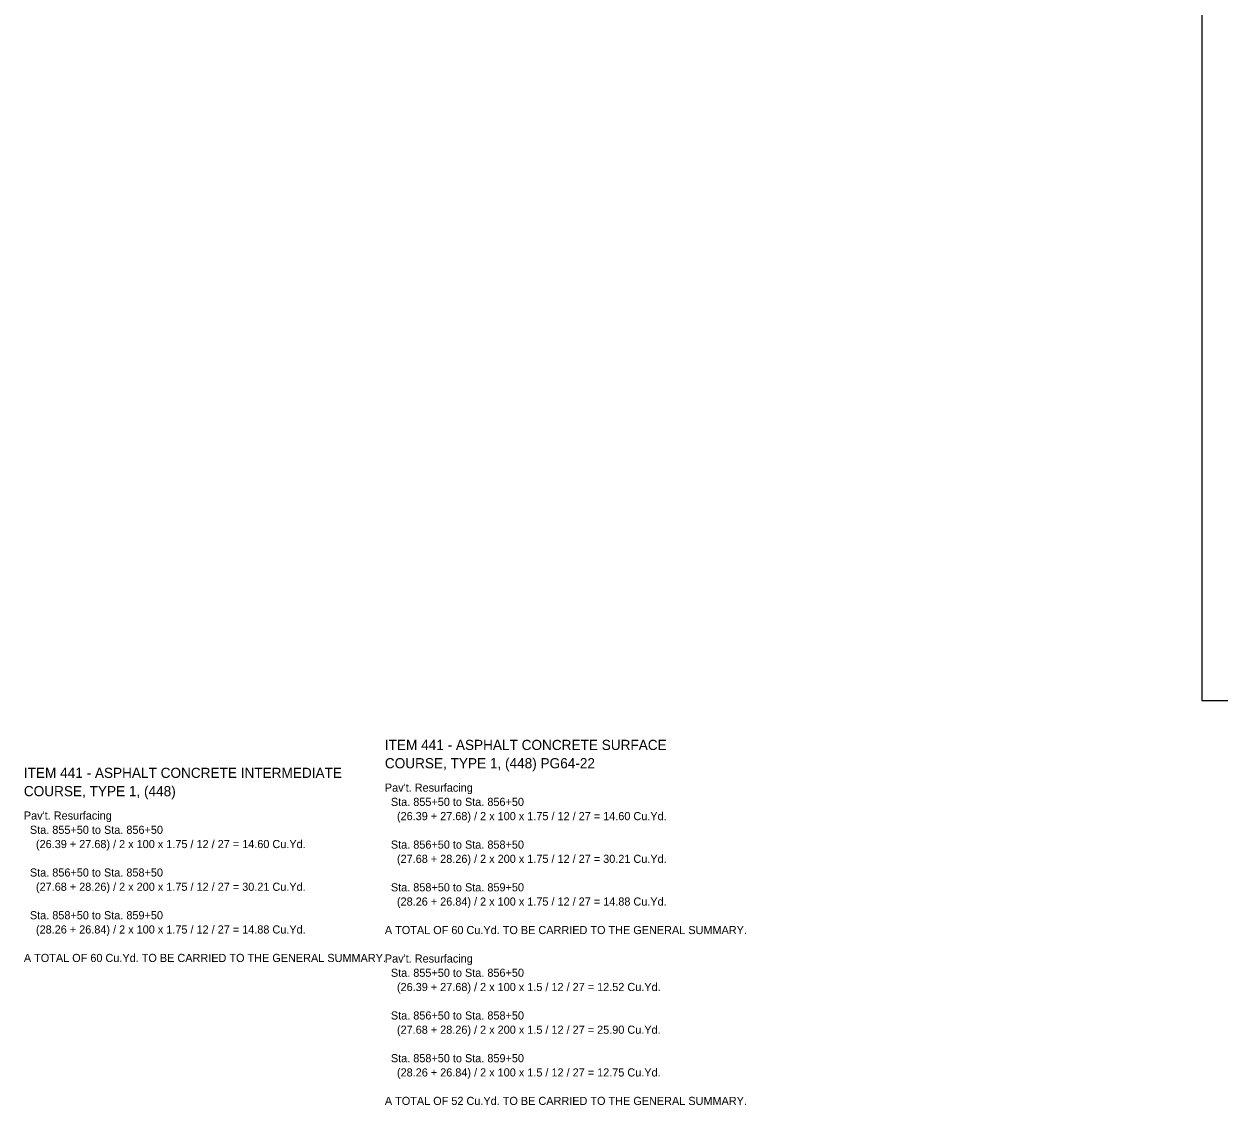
# Model space of a CAD drawing. Extents: x -40.7 to 43.6, y -9.8 to 57.4.
# Drawn here: x -23.17 to 0.34, y -7.95 to 13.31 of the extents above; entities that cross this region are included whole.
import ezdxf

# ---------------------------------------------------------------- set-up
doc = ezdxf.new("R2010")
doc.units = 0
doc.layers.add('Default', color=7, linetype='Continuous')
doc.layers.add('SH_Cut_Line', color=7, linetype='Continuous')

msp = doc.modelspace()

# ---------------------------------------------------------------- linework, layer by layer
at = {"layer": 'SH_Cut_Line'}
msp.add_lwpolyline([(0, 0), (34, 0), (34, 22), (0, 22)], close=True, dxfattribs=at)

# ---------------------------------------------------------------- texts
at = {"layer": 'Default'}
for s, height, p in [('ITEM 441 - ASPHALT CONCRETE SURFACE', 0.2, (-16.07, -0.971)), ('COURSE, TYPE 1, (448) PG64-22', 0.2, (-16.07, -1.331)), ('ITEM 441 - ASPHALT CONCRETE INTERMEDIATE', 0.2, (-23.17, -1.52)), ("Pav't. Resurfacing", 0.16, (-16.07, -1.791)), ('COURSE, TYPE 1, (448)', 0.2, (-23.17, -1.88)), ('  Sta. 855+50 to Sta. 856+50', 0.16, (-16.07, -2.071)), ("Pav't. Resurfacing", 0.16, (-23.17, -2.34)), ('    (26.39 + 27.68) / 2 x 100 x 1.75 / 12 / 27 = 14.60 Cu.Yd.', 0.16, (-16.07, -2.351)), ('  Sta. 855+50 to Sta. 856+50', 0.16, (-23.17, -2.62)), ('    (26.39 + 27.68) / 2 x 100 x 1.75 / 12 / 27 = 14.60 Cu.Yd.', 0.16, (-23.17, -2.9)), ('  Sta. 856+50 to Sta. 858+50', 0.16, (-16.07, -2.911)), ('    (27.68 + 28.26) / 2 x 200 x 1.75 / 12 / 27 = 30.21 Cu.Yd.', 0.16, (-16.07, -3.191)), ('  Sta. 856+50 to Sta. 858+50', 0.16, (-23.17, -3.46)), ('    (27.68 + 28.26) / 2 x 200 x 1.75 / 12 / 27 = 30.21 Cu.Yd.', 0.16, (-23.17, -3.74)), ('  Sta. 858+50 to Sta. 859+50', 0.16, (-16.07, -3.751)), ('    (28.26 + 26.84) / 2 x 100 x 1.75 / 12 / 27 = 14.88 Cu.Yd.', 0.16, (-16.07, -4.031)), ('  Sta. 858+50 to Sta. 859+50', 0.16, (-23.17, -4.3)), ('    (28.26 + 26.84) / 2 x 100 x 1.75 / 12 / 27 = 14.88 Cu.Yd.', 0.16, (-23.17, -4.58)), ('A TOTAL OF 60 Cu.Yd. TO BE CARRIED TO THE GENERAL SUMMARY.', 0.16, (-16.07, -4.591)), ('A TOTAL OF 60 Cu.Yd. TO BE CARRIED TO THE GENERAL SUMMARY.', 0.16, (-23.17, -5.14)), ("Pav't. Resurfacing", 0.16, (-16.07, -5.151)), ('  Sta. 855+50 to Sta. 856+50', 0.16, (-16.07, -5.431)), ('    (26.39 + 27.68) / 2 x 100 x 1.5 / 12 / 27 = 12.52 Cu.Yd.', 0.16, (-16.07, -5.711)), ('  Sta. 856+50 to Sta. 858+50', 0.16, (-16.07, -6.271)), ('    (27.68 + 28.26) / 2 x 200 x 1.5 / 12 / 27 = 25.90 Cu.Yd.', 0.16, (-16.07, -6.551)), ('  Sta. 858+50 to Sta. 859+50', 0.16, (-16.07, -7.111)), ('    (28.26 + 26.84) / 2 x 100 x 1.5 / 12 / 27 = 12.75 Cu.Yd.', 0.16, (-16.07, -7.391)), ('A TOTAL OF 52 Cu.Yd. TO BE CARRIED TO THE GENERAL SUMMARY.', 0.16, (-16.07, -7.951))]:
    msp.add_text(s, height=height, dxfattribs=at).set_placement(p)

doc.saveas('drawing.dxf')
